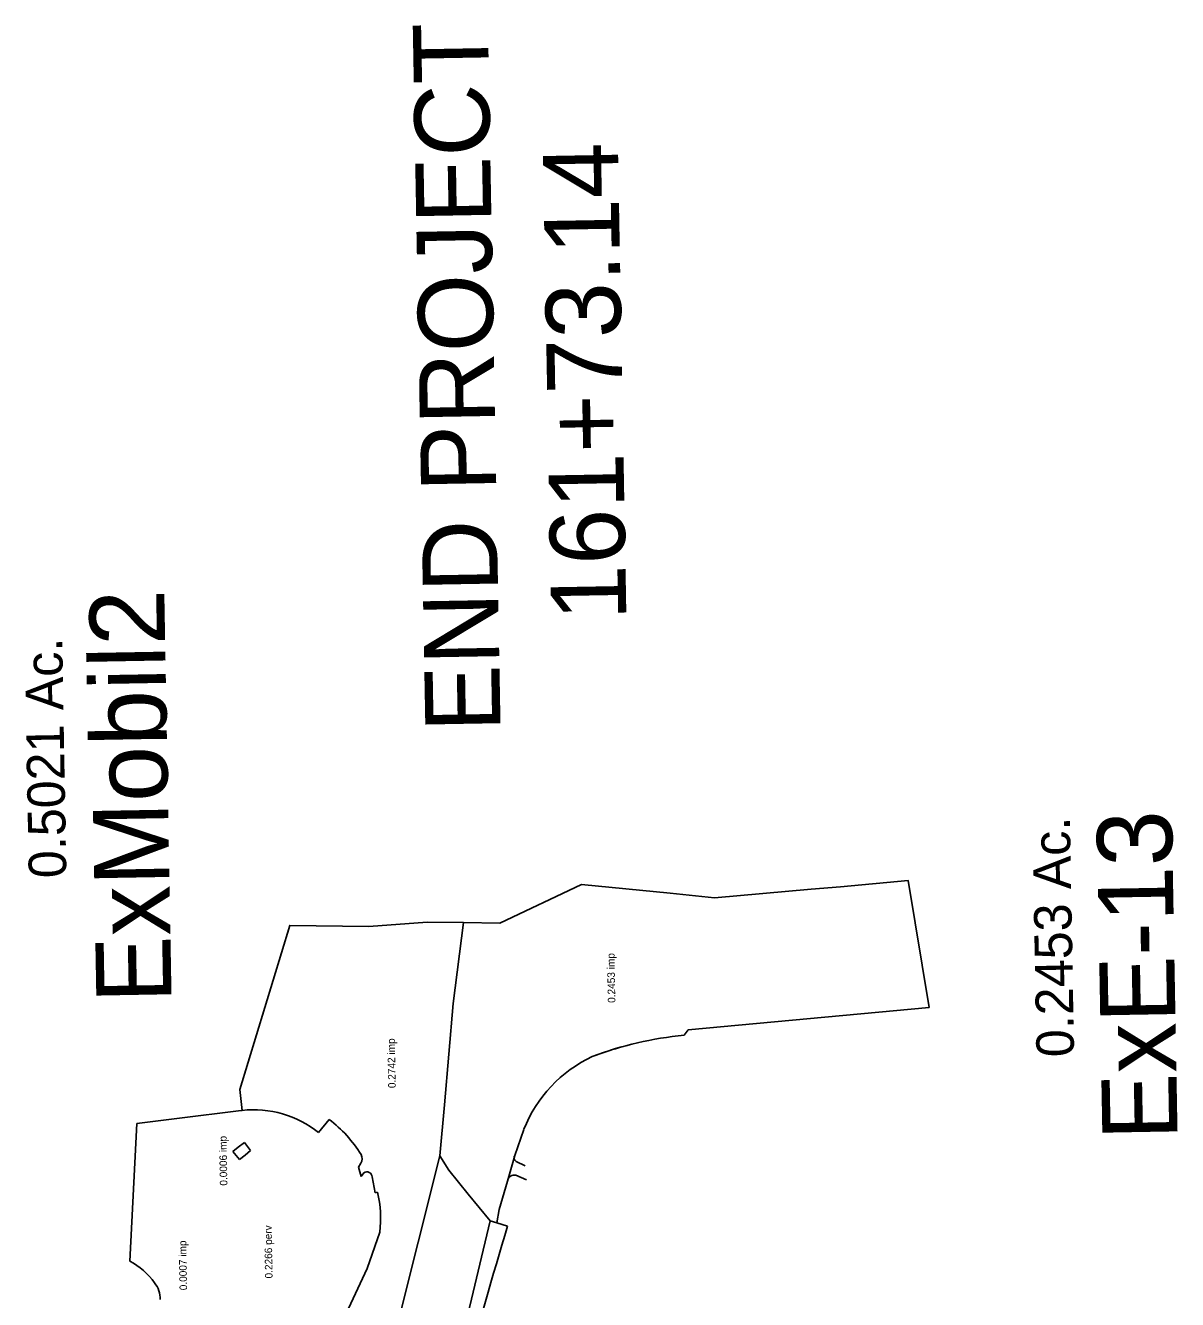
# Model space of a CAD drawing. Extents: x 925564 to 926134, y 853260 to 858402.
# Drawn here: x 925704.8 to 926133.7, y 857927.7 to 858402.1 of the extents above; entities that cross this region are included whole.
import ezdxf

# ---------------------------------------------------------------- set-up
doc = ezdxf.new("R2010")
doc.units = 0
for name, color, linetype in [('DrainDivides01', 7, 'Continuous'), ('PavtMisc_ep', 7, 'Continuous'), ('TextLabel', 7, 'Continuous')]:
    doc.layers.add(name, color=color, linetype=linetype)

msp = doc.modelspace()

# ---------------------------------------------------------------- linework, layer by layer
at = {"layer": 'DrainDivides01'}
for p, q in [((925951.48, 858028.19), (926041.26, 858036.47)), ((925950, 858026.12), (925951.48, 858028.19)), ((925761.15, 857995.14), (925785.1, 857998.09)), ((925785.1, 857998.09), (925785.47, 857998.13)), ((925746.29, 857993.27), (925761.15, 857995.14)), ((925886.96, 857981.41), (925890.4, 857991.1)), ((925859.1, 857981.28), (925830.19, 857866.43)), ((925884.21, 857971.86), (925886.96, 857981.41)), ((925881.2, 857961.19), (925884.21, 857971.86)), ((925880.26, 857956.23), (925881.2, 857961.19)), ((925880.26, 857956.23), (925884.31, 857955))]:
    msp.add_line(p, q, dxfattribs=at)
for points in [[(925867.88, 858068.09), (925881.46, 858067.9), (925911.87, 858082.25), (925928.35, 858080.62), (925944.82, 858078.99), (925961.3, 858077.35), (925997.25, 858080.47), (926008.17, 858081.38), (926033.38, 858083.76), (926041.26, 858036.47)], [(925785.47, 857998.13), (925784.59, 858005.98), (925803.23, 858067.01), (925832.64, 858066.65), (925854.38, 858068.27), (925867.88, 858068.09)], [(925859.1, 857981.28), (925860.77, 858000.18), (925862.43, 858019.08), (925864.1, 858037.97), (925867.88, 858068.09)], [(925743.68, 857942.06), (925746.29, 857993.27)], [(925859.1, 857981.28), (925862.4, 857975.92), (925866.01, 857971.42), (925869.62, 857966.92), (925877.86, 857957.08), (925880.26, 857956.23)]]:
    msp.add_lwpolyline(points, dxfattribs=at)
msp.add_arc((927874.19, 857352.82), 2079, 163.16294, 166.38054, dxfattribs=at)
for centre, major_axis, ratio, start_param, end_param in [((925961.47, 857899.52), (-125.38, -25.91), 0.992736, 4.599832, 4.874706), ((925961.47, 857899.52), (-125.38, -25.91), 0.992736, 4.779472, 4.874706), ((925937.09, 857972.71), (-49.09, -10.45), 0.999917, 4.940147, 5.698181), ((925730.92, 857918.3), (-8.94, 25.46), 0.999069, 4.99165, 5.451876), ((925745.63, 857928.03), (-8.64, 3.59), 0.999824, 3.504431, 4.215651)]:
    msp.add_ellipse(centre, major_axis=major_axis, ratio=ratio, start_param=start_param, end_param=end_param, dxfattribs=at)
at = {"layer": 'PavtMisc_ep'}
for p, q in [((925813.97, 857989.88), (925817.82, 857994.78)), ((925784.03, 857984.49), (925782.06, 857982.85)), ((925782.06, 857982.85), (925784.56, 857979.86)), ((925786.41, 857986.2), (925784.03, 857984.49)), ((925788.64, 857983.23), (925786.41, 857986.2)), ((925786.57, 857981.49), (925788.64, 857983.23)), ((925784.56, 857979.86), (925786.57, 857981.49)), ((925829.64, 857978.49), (925828.79, 857977.06)), ((925828.79, 857977.06), (925829.79, 857973.59)), ((925890.86, 857977.47), (925887.44, 857979.15)), ((925830.8, 857974.89), (925829.79, 857973.59)), ((925834.95, 857967.49), (925833.88, 857973.41)), ((925887.42, 857973.99), (925891.36, 857972.26)), ((925835.9, 857967.66), (925834.95, 857967.49)), ((925877.86, 857957.08), (925855.06, 857861.93)), ((925836.73, 857952.8), (925832.05, 857939.32)), ((925832.05, 857939.32), (925819.14, 857911.81))]:
    msp.add_line(p, q, dxfattribs=at)
for centre, major_axis, ratio, start_param, end_param in [((925789.87, 857959.99), (2.01, -38.34), 0.999985, 2.410612, 3.204268), ((925790.21, 857957.63), (-46.19, -2.94), 0.999982, 3.624485, 4.009619), ((925827.37, 857980.17), (-2.23, 1.73), 0.999411, 3.165183, 4.36923), ((925888.25, 857980.53), (-0.27, -1.59), 0.966095, 4.299236, 5.911055), ((925831.94, 857973.31), (0.39, -1.91), 0.995939, 1.422418, 3.565498), ((925886.68, 857971.59), (-1.09, -2.26), 0.985238, 3.291446, 5.046515), ((925793.57, 857957.84), (-4.64, 43.29), 0.998142, 4.489881, 4.833395)]:
    msp.add_ellipse(centre, major_axis=major_axis, ratio=ratio, start_param=start_param, end_param=end_param, dxfattribs=at)

# ---------------------------------------------------------------- texts
at = {"layer": 'TextLabel'}
for s, height, p in [('END PROJECT ', 28, (925881.71, 858139.26)), ('161+73.14', 28, (925928.55, 858180.7)), ('ExMobil2', 28, (925759.24, 858038.33)), ('0.5021 Ac.', 14, (925720.08, 858084.73)), ('0.2453 Ac.', 14, (926095.21, 858018.08)), ('ExE-13', 28, (926133.74, 857987.28)), ('0.2453 imp', 2.8, (925924.42, 858038.22)), ('0.2742 imp', 2.8, (925842.66, 858006.47)), ('0.0006 imp', 2.8, (925780, 857970.15)), ('0.2266 perv', 2.8, (925796.83, 857935.61)), ('0.0007 imp', 2.8, (925764.99, 857931.21))]:
    msp.add_text(s, height=height, rotation=91.0261, dxfattribs=at).set_placement(p)

doc.saveas('drawing.dxf')
